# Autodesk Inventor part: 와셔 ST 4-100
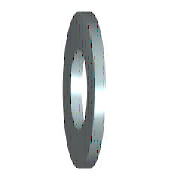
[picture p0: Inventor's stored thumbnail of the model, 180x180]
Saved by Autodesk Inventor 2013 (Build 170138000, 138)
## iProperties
IsCustomPart: 0
Created: 2012-02
Part Number: 와셔 ST 4-100
Material: 강철, 연강
Description: 평면 와셔 - 일반 시리즈 - 제품 등급 C
Document SubType Name: Modeling
Standard: ISO 7091
Designer: mduedu
Standard Revision: Second edition 2000-06-01
Standards Organization: ISO
Language: ko-KR
Size Designation: ST 4 - 100 HV
Categories: <MemberInstance><Categories><Category DisplayName="조임쇠" InternalName="e4da775c-781d-43d5-af7c-5136215cf5a6" Mnemonic="FSTN"><Category DisplayName="와셔" InternalN
Density: 8.83 g/cm^3
Mass: 0.553071 g
Surface Area: 1.70824 cm^2
Volume: 0.0626355 cm^3
Author: mduedu
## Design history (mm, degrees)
sketch "스케치"
  geometry: C1 r 5 at (0, 0); C2 r 2.25 at (0, 0); 1 further point
  constraints: 2 centre point, 2 coincident
  dimensions: "d0" = 4.5 diameter of C2 (= SD1); "d1" = 10 diameter of C1 (= SD2)
extrude "본체" new body sketch "스케치" distance "d2" = 1 (= SD); taper "d3" = 0 deg
workaxis "Work Axis1"
workplane "Work Plane1"
body "Solid1"
other parameters: "SD1" = 4.5 [user parameter; used in 1 equation term], "SD2" = 10 [user parameter; used in 1 equation term], "SD" = 1 [user parameter; used in 1 equation term], "d4" = 0, "d5" = 0, "d6" = 0, "d7" = 0, "NND" = 4 [user parameter]
